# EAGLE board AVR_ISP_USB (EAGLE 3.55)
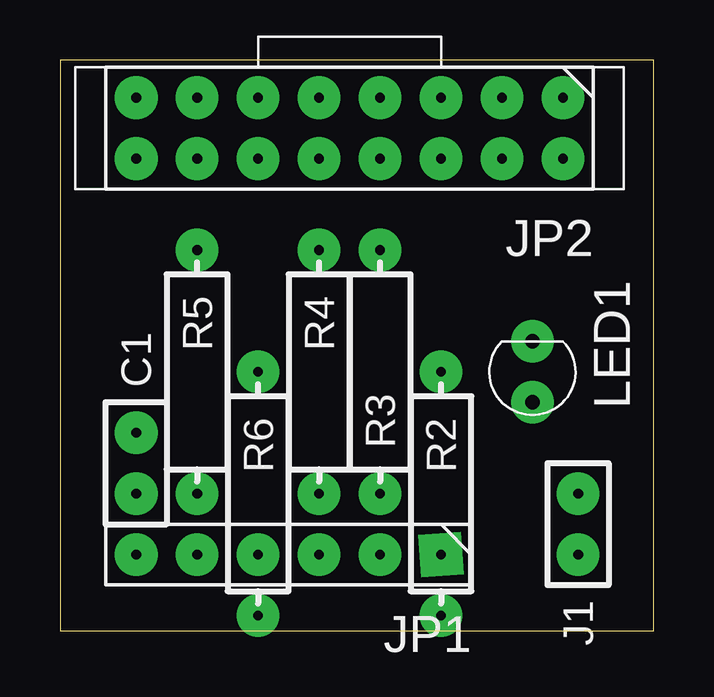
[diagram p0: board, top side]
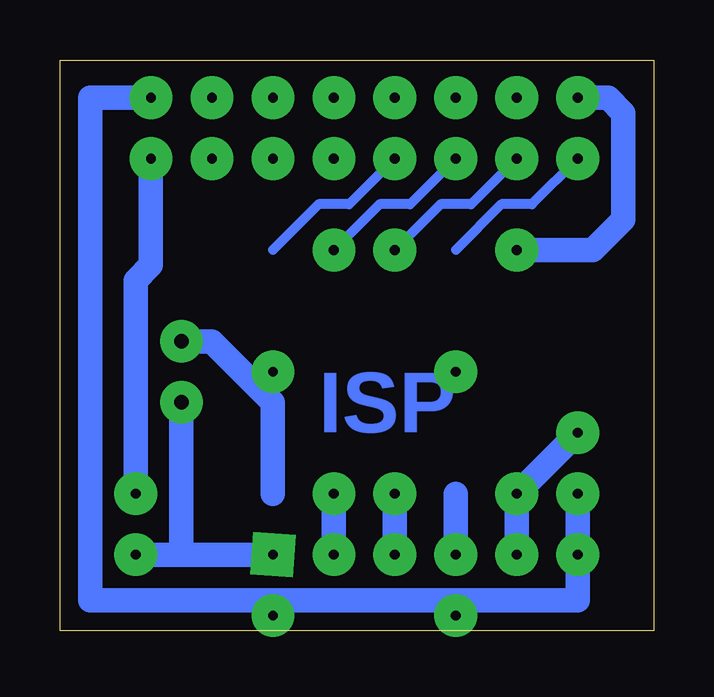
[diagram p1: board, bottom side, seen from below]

Size 24.75 x 23.8 mm. Coordinates in mm from the lower left corner, seen from the top.
Outline: 0,0 24.75,0 24.75,23.8 0,23.8 0,0
Copper layers used: Bottom

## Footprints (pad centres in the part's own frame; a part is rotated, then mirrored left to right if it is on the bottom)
RM2,5 = drill 0.406 pad 1.778 round:  0,0;  2.54,0
MPER = drill 0.406 pad 1.778 round:  -1.27,0;  1.27,0
6 = drill 0.406 pad 1.778 square:  0,0 | drill 0.406 pad 1.778 round:  5.08,0;  10.16,0;  12.7,0;  7.62,0;  2.54,0
8 = drill 0.406 pad 1.778 round:  -8.89,-1.27;  -6.35,-1.27;  -3.81,-1.27;  -1.27,-1.27;  1.27,-1.27;  1.27,1.27;  -1.27,1.27;  -3.81,1.27;  -6.35,1.27;  -8.89,1.27;  3.81,-1.27;  3.81,1.27;  6.35,-1.27;  6.35,1.27;  8.89,-1.27;  8.89,1.27
D_3MM = drill 0.61 pad 1.778 round:  -1.27,0;  1.27,0
S04 = drill 0.406 pad 1.778 round:  0,0;  10.16,0

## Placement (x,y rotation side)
C1  100p  [RM2,5]  3.17,5.71 90 top
J1  JUMPER  [MPER]  21.59,4.45 270 top
JP1  PINHD-1X6  [6]  15.88,3.17 180 top
JP2  PINHD-2X8  [8]  12.06,20.95 180 top
LED1  Program  [D_3MM]  19.68,10.79 90 top
R2  470  [S04]  15.88,10.79 270 top
R3  220  [S04]  13.34,5.71 90 top
R4  220  [S04]  10.79,15.88 270 top
R5  220  [S04]  5.71,15.88 270 top
R6  220  [S04]  8.26,10.79 270 top

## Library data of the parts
C1 J1 JP1 JP2 LED1 R2-R6 = holg_plt

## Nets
/RESET: JP2. R3.
GND: C1. JP1. JP2.
MISO: JP1. R6.
MOSI: JP2. R4.
N$1: C1. JP1. R5.
N$2: JP2. R6.
N$3: JP2. R2.
N$4: JP1. R3.
N$5: J1. JP1. LED1.
N$6: JP1. R4.
N$7: LED1. R2.
N$8: J1. JP2.
SCK: JP2. R5.

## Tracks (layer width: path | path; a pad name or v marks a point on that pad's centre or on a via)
/RESET
  Bottom 0.406: 8.26,19.68 10.16,17.78 11.43,17.78 R3.
GND
  Bottom 1.016: 3.17,5.71 3.17,3.17 3.17,1.27 23.5,1.27 23.5,22.23 20.95,22.23
MISO
  Bottom 1.016: 8.26,3.17 8.26,5.71
MOSI
  Bottom 0.406: 5.71,19.68 7.62,17.78 8.89,17.78 10.79,15.88
N$1
  Bottom 1.016: 5.71,3.17 R5. C1.
N$2
  Bottom 0.406: JP2. 5.08,17.78 6.35,17.78 8.26,15.88
N$3
  Bottom 0.406: 10.79,19.68 12.7,17.78 13.97,17.78 15.88,15.88
N$4
  Bottom 1.016: JP1. 13.34,5.71
N$5
  Bottom 1.016: 15.88,3.17 19.68,3.17 | 19.68,3.17 J1. | 19.68,3.17 19.68,9.53
N$6
  Bottom 1.016: 10.79,3.17 R4.
N$7
  Bottom 1.016: LED1. 18.41,12.06 15.88,9.53 15.88,5.71
N$8
  Bottom 1.016: 21.59,5.71 21.59,14.61 20.95,15.24 20.95,19.68
SCK
  Bottom 1.016: 5.71,15.88 2.54,15.88 1.27,17.14 1.27,21.59 1.91,22.23 3.17,22.23

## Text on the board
Bottom: ISP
